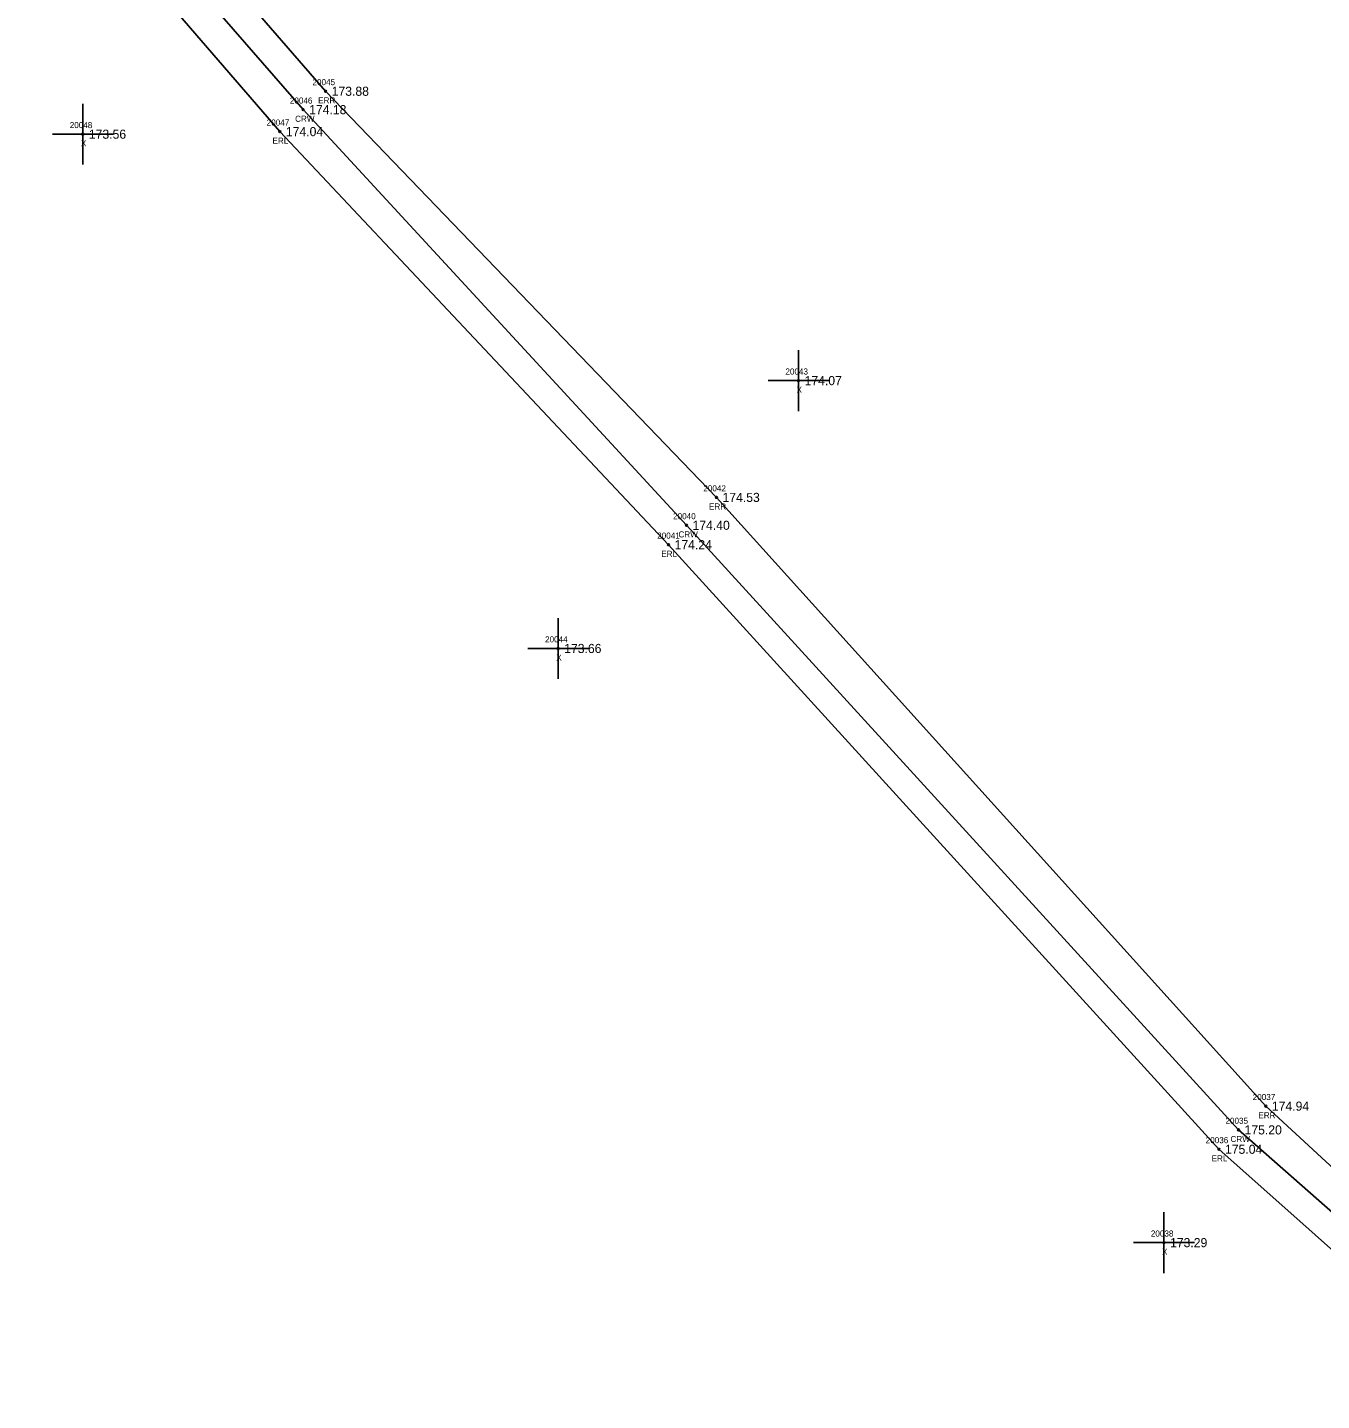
# Model space of a CAD drawing. Extents: x 1970726 to 1971567, y 794829 to 795775.
# Drawn here: x 1970968.9 to 1971181.9, y 795072.6 to 795298.6 of the extents above; entities that cross this region are included whole.
import ezdxf

# ---------------------------------------------------------------- set-up
doc = ezdxf.new("R2010")
doc.units = 0
for name, color, linetype in [('RD_DTM_BkLn1', 7, 'Continuous'), ('RD_EX_Misc', 7, 'Continuous'), ('RD_EX_Misc_txCode', 7, 'Continuous'), ('RD_EX_Road', 7, 'Continuous'), ('RD_EX_Road_txCode', 7, 'Continuous'), ('RD_EX_TX_Misc_ELEV', 7, 'Continuous'), ('RD_EX_TX_Road_ELEV', 7, 'Continuous'), ('RD_HC_Survey_ELEV', 7, 'Continuous'), ('RD_HC_Survey_txCode', 7, 'Continuous'), ('RD_SMD_Locator', 7, 'Continuous')]:
    doc.layers.add(name, color=color, linetype=linetype)

msp = doc.modelspace()

# ---------------------------------------------------------------- linework, layer by layer
at = {"layer": 'RD_DTM_BkLn1'}
msp.add_lwpolyline([(1971548, 794856.6), (1971469.65, 794899.39), (1971398.6, 794938.78), (1971343.49, 794971.52), (1971282.15, 795020.93), (1971214.82, 795076.24), (1971168.26, 795117.15), (1971077.37, 795216.68), (1971014.25, 795285.1), (1970928, 795384.12), (1970874.41, 795450.05), (1970851.19, 795487.2), (1970834.94, 795528.12), (1970822.6, 795571.11), (1970808.56, 795633.3), (1970801.01, 795695.48), (1970787.01, 795762.98)], dxfattribs=at)
at = {"layer": 'RD_EX_Misc'}
for p, q in [((1970977.98, 795276.06), (1970977.98, 795286.06)), ((1970972.98, 795281.06), (1970982.98, 795281.06)), ((1971095.82, 795235.49), (1971095.82, 795245.49)), ((1971090.82, 795240.49), (1971100.82, 795240.49)), ((1971056.24, 795191.4), (1971056.24, 795201.4)), ((1971051.24, 795196.4), (1971061.24, 795196.4)), ((1971155.99, 795093.59), (1971155.99, 795103.59)), ((1971150.99, 795098.59), (1971160.99, 795098.59))]:
    msp.add_line(p, q, dxfattribs=at)
at = {"layer": 'RD_EX_Road'}
for points in [[(1971550.5, 794861.13), (1971472.2, 794904.32), (1971401.49, 794943.08), (1971346.58, 794975.73), (1971286.05, 795024.56), (1971217.92, 795079.41), (1971172.76, 795121.06), (1971082.31, 795221.27), (1971017.96, 795288.13), (1970931.75, 795387.33), (1970878.11, 795452.95), (1970856.35, 795489.48), (1970840.29, 795529.45), (1970827.57, 795574.31), (1970814.81, 795635.62), (1970805.04, 795696.13), (1970791.39, 795763.83)], [(1971543.68, 794851.6), (1971507.7, 794872.08), (1971504.76, 794847.96), (1971494.98, 794846.56), (1971488.18, 794883), (1971469.72, 794893.79), (1971395.92, 794934.76), (1971339.47, 794967.38), (1971278.34, 795016.59), (1971212.1, 795072.1), (1971165.04, 795113.96), (1971074.42, 795213.48), (1971010.42, 795281.48), (1970922.49, 795383.19), (1970882.25, 795365.41), (1970854.66, 795404.07), (1970871.45, 795443.76), (1970844.39, 795483.83), (1970828.93, 795526.65), (1970817.76, 795568.61), (1970806.82, 795600.57), (1970787.72, 795602.49), (1970770.58, 795591.56)]]:
    msp.add_lwpolyline(points, dxfattribs=at)
at = {"layer": 'RD_SMD_Locator'}
for centre in [(1971017.96, 795288.13), (1971014.25, 795285.1), (1971010.42, 795281.48), (1970977.98, 795281.06), (1971095.82, 795240.49), (1971082.31, 795221.27), (1971077.37, 795216.68), (1971074.42, 795213.48), (1971056.24, 795196.4), (1971172.76, 795121.06), (1971168.26, 795117.15), (1971165.04, 795113.96), (1971155.99, 795098.59)]:
    msp.add_circle(centre, 0.15, dxfattribs=at)

# ---------------------------------------------------------------- texts
at = {"layer": 'RD_EX_Misc_txCode'}
for s, p in [('20048', (1970975.83, 795282.06)), ('X', (1970977.67, 795279.06)), ('20043', (1971093.66, 795241.49)), ('X', (1971095.5, 795238.49)), ('20044', (1971054.09, 795197.4)), ('X', (1971055.93, 795194.4)), ('20038', (1971153.83, 795099.59)), ('X', (1971155.67, 795096.59))]:
    msp.add_text(s, height=1, dxfattribs=at).set_placement(p)
at = {"layer": 'RD_EX_Road_txCode'}
for s, p in [('20045', (1971015.8, 795289.13)), ('ERR', (1971016.73, 795286.13)), ('20047', (1971008.26, 795282.48)), ('ERL', (1971009.21, 795279.48)), ('20042', (1971080.15, 795222.27)), ('ERR', (1971081.08, 795219.27)), ('20041', (1971072.55, 795214.48)), ('ERL', (1971073.22, 795211.48)), ('20037', (1971170.6, 795122.06)), ('ERR', (1971171.53, 795119.06)), ('20036', (1971162.86, 795114.96)), ('ERL', (1971163.83, 795111.96))]:
    msp.add_text(s, height=1, dxfattribs=at).set_placement(p)
at = {"layer": 'RD_EX_TX_Misc_ELEV'}
for s, p in [('173.56', (1970978.98, 795280.31)), ('174.07', (1971096.82, 795239.74)), ('173.66', (1971057.24, 795195.65)), ('173.29', (1971156.99, 795097.84))]:
    msp.add_text(s, height=1.5, dxfattribs=at).set_placement(p)
at = {"layer": 'RD_EX_TX_Road_ELEV'}
for s, p in [('173.88', (1971018.96, 795287.38)), ('174.04', (1971011.42, 795280.73)), ('174.53', (1971083.31, 795220.52)), ('174.24', (1971075.42, 795212.73)), ('174.94', (1971173.76, 795120.31)), ('175.04', (1971166.04, 795113.21))]:
    msp.add_text(s, height=1.5, dxfattribs=at).set_placement(p)
at = {"layer": 'RD_HC_Survey_ELEV'}
for s, p in [('174.18', (1971015.25, 795284.35)), ('174.40', (1971078.37, 795215.93)), ('175.20', (1971169.26, 795116.4))]:
    msp.add_text(s, height=1.5, dxfattribs=at).set_placement(p)
at = {"layer": 'RD_HC_Survey_txCode'}
for s, p in [('20046', (1971012.07, 795286.1)), ('CRW', (1971012.94, 795283.1)), ('20040', (1971075.17, 795217.68)), ('CRW', (1971076.05, 795214.68)), ('20035', (1971166.11, 795118.15)), ('CRW', (1971166.95, 795115.15))]:
    msp.add_text(s, height=1, dxfattribs=at).set_placement(p)

doc.saveas('drawing.dxf')
